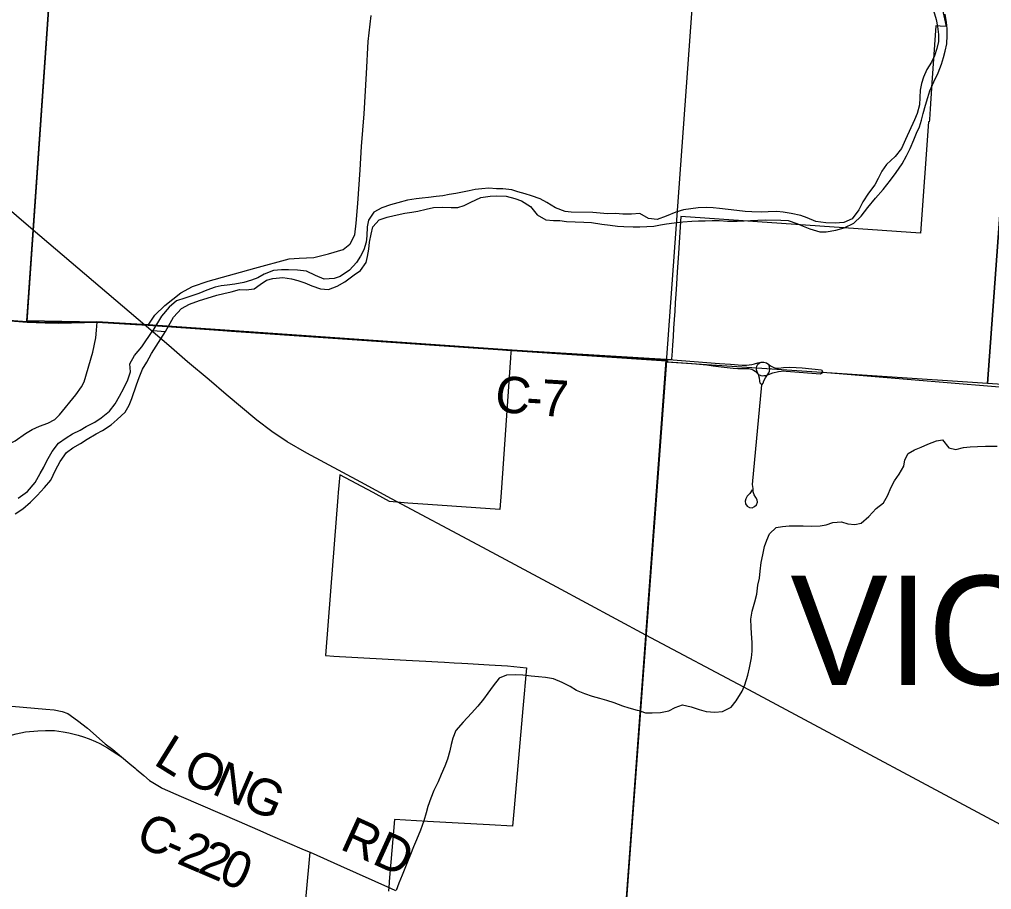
# Model space of a CAD drawing. Extents: x 0 to 34, y 0 to 22.
# Drawn here: x 2.165 to 3.682, y 15.435 to 16.793 of the extents above; entities that cross this region are included whole.
import ezdxf

# ---------------------------------------------------------------- set-up
doc = ezdxf.new("R2010")
doc.units = 0
for name, color, linetype in [('GM_X_City_Street', 7, 'Continuous'), ('GM_X_Corporation', 7, 'Continuous'), ('GM_X_County', 7, 'Continuous'), ('GM_X_County_Road', 7, 'Continuous'), ('GM_X_County_Road_Text', 7, 'Continuous'), ('GM_X_Minor_River', 7, 'Continuous'), ('GM_X_Rail_Line', 7, 'Continuous'), ('GM_X_Township_Road', 7, 'Continuous'), ('GM_X_Township_Text', 7, 'Continuous')]:
    doc.layers.add(name, color=color, linetype=linetype)

msp = doc.modelspace()

# ---------------------------------------------------------------- linework, layer by layer
at = {"layer": 'GM_X_City_Street'}
for p, q in [((2.1, 16.3267), (2.177, 16.3208)), ((2.2862, 16.3208), (2.346, 16.3171)), ((2.346, 16.3171), (2.356, 16.3165)), ((2.356, 16.3165), (2.366, 16.3159)), ((2.366, 16.3159), (2.4758, 16.3083)), ((2.4758, 16.3083), (2.4958, 16.3069)), ((2.4958, 16.3069), (2.8651, 16.2813)), ((2.8651, 16.2813), (2.912, 16.278)), ((2.912, 16.278), (2.925, 16.2771))]:
    msp.add_line(p, q, dxfattribs=at)
for points in [[(2.1, 16.1061), (2.1006, 16.1068), (2.1101, 16.1137), (2.1198, 16.1188), (2.1456, 16.129), (2.1584, 16.1355), (2.1745, 16.1467), (2.1851, 16.1533), (2.1964, 16.1584), (2.2094, 16.1632), (2.22, 16.1689), (2.2277, 16.1759), (2.2528, 16.2074), (2.2618, 16.2199), (2.266, 16.2274), (2.2797, 16.274), (2.2844, 16.2963), (2.2852, 16.3083), (2.2862, 16.3208)], [(2.177, 16.3208), (2.2054, 16.3195), (2.2266, 16.3194), (2.2862, 16.3208)], [(2.925, 16.2771), (2.934, 16.2765), (3.1745, 16.2606)], [(3.3184, 16.239), (3.316, 16.2432), (3.3151, 16.2465), (3.315, 16.249), (3.3156, 16.2519), (3.3172, 16.2551), (3.3193, 16.2568), (3.3222, 16.2584)], [(3.3325, 16.2385), (3.3346, 16.2416), (3.3354, 16.2442), (3.3359, 16.2476), (3.3356, 16.2509), (3.3343, 16.2548)], [(3.3232, 16.2229), (3.3207, 16.2255), (3.3204, 16.2294), (3.3199, 16.2332), (3.3184, 16.239)], [(3.3232, 16.2229), (3.3257, 16.2253), (3.3267, 16.2292), (3.3289, 16.234), (3.3325, 16.2385)], [(3.3083, 16.0592), (3.3047, 16.0532), (3.3007, 16.0489), (3.2985, 16.0451), (3.2976, 16.0413), (3.2979, 16.0372), (3.3006, 16.0336), (3.3043, 16.0313), (3.3084, 16.0311), (3.3122, 16.033), (3.315, 16.0357), (3.3167, 16.0399), (3.316, 16.0436), (3.3139, 16.0472), (3.3115, 16.0513), (3.31, 16.0559), (3.31, 16.0611), (3.3089, 16.0674), (3.3232, 16.2229)], [(2.1, 15.6513), (2.1025, 15.6529), (2.1199, 15.6632), (2.134, 15.6695), (2.1483, 15.6747), (2.1597, 15.6778), (2.1745, 15.681), (2.1937, 15.6829), (2.2057, 15.6834), (2.212, 15.6834), (2.2195, 15.6831), (2.233, 15.6813), (2.2422, 15.6795), (2.2567, 15.6757), (2.2652, 15.6731), (2.2738, 15.67), (2.2836, 15.666), (2.2905, 15.6627), (2.3025, 15.6563), (2.3241, 15.6421)]]:
    msp.add_lwpolyline(points, dxfattribs=at)
at = {"layer": 'GM_X_Corporation'}
for points in [[(4.3071, 20.9), (2.1, 20.9), (2.1, 14.1), (3.0169, 14.1), (3.0406, 14.4484), (3.1026, 15.287), (3.1745, 16.2606), (2.934, 16.2765), (2.366, 16.3159), (2.2862, 16.3208), (2.1768, 16.323), (2.2478, 17.3472), (2.3155, 18.3567), (3.8153, 18.2543), (3.8503, 18.7566), (3.8611, 18.9124), (3.8924, 19.3621), (3.9019, 19.4987), (3.9133, 19.6628), (3.9816, 20.645), (3.9912, 20.7822), (4.2975, 20.7549)], [(3.2481, 17.2693), (3.7496, 17.2367), (3.6755, 16.2252), (3.1745, 16.2581)], [(3.7496, 17.2367), (4.2556, 17.2022), (4.1846, 16.1905), (3.6755, 16.2252)], [(2.1, 16.3272), (2.1, 14.1), (3.0167, 14.1), (3.0404, 14.449), (3.1023, 15.2875), (3.1743, 16.2612), (2.9338, 16.2771), (2.3658, 16.3164), (2.2859, 16.3213), (2.2263, 16.32), (2.2052, 16.32), (2.1768, 16.3213)]]:
    msp.add_lwpolyline(points, close=True, dxfattribs=at)
for points in [[(2.1, 20.8993), (2.1, 16.3272), (2.1768, 16.3213), (2.1816, 16.3969), (2.2476, 17.3477), (2.2711, 17.6998), (2.2728, 17.718), (2.3153, 18.3572), (3.3358, 18.2876), (3.8151, 18.2549), (3.8501, 18.7572)], [(3.1023, 15.2875), (3.1743, 16.2612), (2.9338, 16.2771), (2.3658, 16.3164), (2.2859, 16.3213), (2.2263, 16.32), (2.2052, 16.32), (2.1768, 16.3213), (2.1816, 16.3969), (2.2476, 17.3477), (2.2711, 17.6998), (2.2728, 17.718), (2.3153, 18.3572), (3.3358, 18.2876), (3.8151, 18.2549), (3.8501, 18.7572)], [(3.8151, 18.2549), (3.3358, 18.2876), (2.3153, 18.3572), (2.2728, 17.718), (2.2711, 17.6998), (2.2476, 17.3477), (2.1816, 16.3969), (2.1768, 16.3213), (2.2052, 16.32), (2.2263, 16.32), (2.2859, 16.3213), (2.3658, 16.3164), (2.9338, 16.2771), (3.1743, 16.2612), (3.1023, 15.2875)], [(3.8151, 18.2549), (3.3358, 18.2876), (2.3153, 18.3572), (2.2728, 17.718), (2.2711, 17.6998), (2.2476, 17.3477), (2.1816, 16.3969), (2.1768, 16.3213), (2.2052, 16.32), (2.2263, 16.32), (2.2859, 16.3213), (2.3658, 16.3164), (2.9338, 16.2771), (3.1743, 16.2612), (3.1023, 15.2875)], [(6.5646, 18.0583), (6.0906, 18.0978), (6.0343, 18.1015), (5.9465, 18.1082), (5.8371, 18.1158), (5.5447, 18.1318), (4.9551, 18.1768), (4.7449, 18.1929), (4.5528, 18.2021), (4.3271, 18.2226), (4.1999, 18.2271), (3.8153, 18.2543), (2.3155, 18.3567), (2.2478, 17.3472), (2.1768, 16.323), (2.2862, 16.3208), (2.366, 16.3159), (2.934, 16.2765), (3.1745, 16.2606), (3.1026, 15.287), (3.0406, 14.4484), (3.0169, 14.1), (8.9, 14.1)], [(3.6049, 16.8109), (3.6112, 16.7822), (3.6112, 16.7822), (3.611, 16.7822), (3.6018, 16.7828), (3.5948, 16.7834), (3.5947, 16.7834), (3.5947, 16.7833), (3.5884, 16.6874), (3.5883, 16.6859), (3.5861, 16.6537), (3.5849, 16.6372), (3.5848, 16.6365), (3.5846, 16.6337), (3.5837, 16.6338), (3.5712, 16.4597), (3.1972, 16.4856), (3.1934, 16.4287), (3.1915, 16.399), (3.1909, 16.3901), (3.1903, 16.3801), (3.1893, 16.3645), (3.1884, 16.3512), (3.1875, 16.338), (3.1867, 16.3248), (3.1858, 16.3115), (3.1849, 16.2983), (3.1841, 16.2851), (3.1829, 16.268), (3.1827, 16.2643), (3.1825, 16.2621), (2.9487, 16.2762), (2.9321, 16.2772), (2.9318, 16.2733), (2.9312, 16.2653), (2.9165, 16.0546), (2.9147, 16.0283), (2.8022, 16.0361), (2.7709, 16.0382), (2.7423, 16.041), (2.7218, 16.0521), (2.717, 16.0546), (2.665, 16.0823), (2.6625, 16.0546), (2.6619, 16.0474), (2.6504, 15.9008), (2.6425, 15.8002), (2.6554, 15.7995), (2.6646, 15.799), (2.6741, 15.7984), (2.6836, 15.7979), (2.693, 15.7974), (2.7025, 15.7968), (2.7119, 15.7963), (2.7217, 15.7957), (2.7308, 15.7952), (2.7403, 15.7947), (2.7497, 15.7942), (2.7592, 15.7936), (2.7686, 15.7931), (2.7781, 15.7926), (2.7885, 15.792), (2.7989, 15.7914), (2.8084, 15.7909), (2.8178, 15.7903), (2.8283, 15.7897), (2.8435, 15.7889), (2.8552, 15.7882), (2.8647, 15.7877), (2.8978, 15.7858), (2.9267, 15.7842), (2.956, 15.7809), (2.9504, 15.7174), (2.9369, 15.5624), (2.9343, 15.5336), (2.8985, 15.5357), (2.8496, 15.5385), (2.8018, 15.5413), (2.7501, 15.5443), (2.7417, 15.4475), (2.7417, 15.4453), (2.7408, 15.4323)]]:
    msp.add_lwpolyline(points, dxfattribs=at)
at = {"layer": 'GM_X_County'}
msp.add_lwpolyline([(3.1023, 15.2875), (3.1743, 16.2612), (2.9338, 16.2771), (2.3658, 16.3164), (2.2859, 16.3213), (2.2263, 16.32), (2.2052, 16.32), (2.1768, 16.3213), (2.1816, 16.3969), (2.2476, 17.3477), (2.2711, 17.6998), (2.2728, 17.718), (2.3153, 18.3572), (3.3358, 18.2876), (3.8151, 18.2549)], dxfattribs=at)
at = {"layer": 'GM_X_County_Road'}
for p, q in [((2.2862, 16.3208), (2.346, 16.3171)), ((2.346, 16.3171), (2.356, 16.3165)), ((2.356, 16.3165), (2.366, 16.3159)), ((2.366, 16.3159), (2.4758, 16.3083)), ((2.4758, 16.3083), (2.4958, 16.3069)), ((2.4958, 16.3069), (2.8651, 16.2813)), ((2.8651, 16.2813), (2.912, 16.278)), ((2.912, 16.278), (2.925, 16.2771)), ((3.4186, 16.2428), (3.4691, 16.2386)), ((2.508, 15.5409), (2.545, 15.5248))]:
    msp.add_line(p, q, dxfattribs=at)
for points in [[(2.925, 16.2771), (2.934, 16.2765), (3.1657, 16.2612), (3.1745, 16.2606)], [(3.1745, 16.2606), (3.1781, 16.2623), (3.2377, 16.2577), (3.2573, 16.2563), (3.2746, 16.2551), (3.2926, 16.2538), (3.2997, 16.2539), (3.3076, 16.2548), (3.312, 16.2559), (3.3173, 16.2575), (3.3222, 16.2584)], [(3.1745, 16.2606), (3.1771, 16.259), (3.2146, 16.2564), (3.2375, 16.2541), (3.2476, 16.2527), (3.2601, 16.251), (3.2692, 16.2498), (3.2786, 16.249), (3.286, 16.2486), (3.2955, 16.2487), (3.3031, 16.2484), (3.3072, 16.2475), (3.3104, 16.246), (3.3128, 16.2441), (3.3145, 16.2425), (3.3184, 16.239)], [(3.3222, 16.2584), (3.3265, 16.2585), (3.3307, 16.2571), (3.3343, 16.2548)], [(3.3343, 16.2548), (3.3368, 16.2526), (3.3409, 16.2503), (3.3446, 16.2491), (3.3493, 16.2491), (3.3571, 16.2499), (3.3669, 16.2503), (3.3772, 16.2501), (3.3863, 16.2495), (3.4163, 16.2463), (3.4186, 16.2428)], [(3.3184, 16.239), (3.3218, 16.2375), (3.3245, 16.2372), (3.3266, 16.2373), (3.33, 16.2376), (3.3325, 16.2385)], [(3.3325, 16.2385), (3.334, 16.2391), (3.3404, 16.2418), (3.3493, 16.2439), (3.3578, 16.2446), (3.3615, 16.2444), (3.4152, 16.2402), (3.4186, 16.2428)], [(3.4691, 16.2386), (3.8317, 16.2085), (3.8733, 16.2068)], [(2.153, 15.7212), (2.2064, 15.7167), (2.2194, 15.7153), (2.2316, 15.7131), (2.2403, 15.7098), (2.2556, 15.6988), (2.271, 15.6867), (2.299, 15.6626), (2.3105, 15.6534), (2.3241, 15.6421)], [(2.3241, 15.6421), (2.3372, 15.631), (2.3454, 15.6242), (2.347, 15.6229)], [(2.347, 15.6229), (2.359, 15.613), (2.368, 15.6054), (2.3782, 15.5987), (2.386, 15.5943), (2.3878, 15.5934)], [(2.3878, 15.5934), (2.4172, 15.5804), (2.508, 15.5409)], [(2.545, 15.5248), (2.5561, 15.52), (2.6094, 15.4971)], [(2.5479, 14.5441), (2.5748, 14.9604), (2.5921, 15.2034), (2.6186, 15.4932)], [(2.6094, 15.4971), (2.6186, 15.4932), (2.6658, 15.4721), (2.7439, 15.4371), (2.7518, 15.4334)]]:
    msp.add_lwpolyline(points, dxfattribs=at)
at = {"layer": 'GM_X_Minor_River'}
for points in [[(3.5914, 16.8072), (3.5954, 16.7934), (3.5975, 16.7824), (3.5992, 16.7702), (3.599, 16.7589), (3.5966, 16.7483), (3.5931, 16.7369), (3.5884, 16.7267), (3.581, 16.7155), (3.5756, 16.7034), (3.5724, 16.6932), (3.5707, 16.683), (3.5698, 16.6716), (3.5693, 16.6602), (3.566, 16.6466), (3.5617, 16.6368), (3.5477, 16.6062), (3.5414, 16.5919), (3.5314, 16.5795), (3.518, 16.5668)], [(3.1749, 16.4744), (3.1867, 16.4761), (3.1999, 16.4774), (3.214, 16.4784), (3.2246, 16.479), (3.2348, 16.4792), (3.2461, 16.4794), (3.2571, 16.4793), (3.2696, 16.4787), (3.2851, 16.4785), (3.2961, 16.4788), (3.3059, 16.4794), (3.3287, 16.4806), (3.3529, 16.4802), (3.3646, 16.4793), (3.3782, 16.4746), (3.3879, 16.4706), (3.3981, 16.4663), (3.4139, 16.4619), (3.4238, 16.4618), (3.4389, 16.4642), (3.4519, 16.4682), (3.4671, 16.4756), (3.4786, 16.4861), (3.4886, 16.4996), (3.5006, 16.5143), (3.5125, 16.5278), (3.5241, 16.5424), (3.5329, 16.5544), (3.5426, 16.568), (3.5492, 16.5804), (3.5547, 16.5921), (3.5605, 16.6053), (3.5648, 16.6158), (3.5692, 16.626), (3.5727, 16.6362), (3.5751, 16.6468), (3.5787, 16.6597), (3.5823, 16.6718), (3.5858, 16.682), (3.5917, 16.6959), (3.5984, 16.7103), (3.6038, 16.7235), (3.607, 16.7341), (3.6094, 16.7439), (3.6119, 16.7556), (3.6128, 16.7682), (3.6126, 16.7788), (3.6116, 16.789), (3.6095, 16.8016)], [(3.518, 16.5668), (3.5106, 16.5566), (3.5052, 16.5449), (3.4997, 16.5351), (3.4901, 16.5224), (3.4808, 16.5088), (3.4746, 16.496), (3.4642, 16.4821), (3.4512, 16.4766), (3.438, 16.4756), (3.4232, 16.4759), (3.4077, 16.478), (3.3942, 16.4835), (3.3844, 16.4874), (3.3693, 16.4903), (3.3568, 16.4927), (3.347, 16.4936), (3.3334, 16.493), (3.3224, 16.4924), (3.308, 16.493), (3.2974, 16.4935), (3.2842, 16.4949), (3.271, 16.4966), (3.2574, 16.4983), (3.2476, 16.4992), (3.237, 16.4997), (3.2241, 16.4991), (3.2127, 16.4977), (3.201, 16.496), (3.1892, 16.4928), (3.1743, 16.4865), (3.1599, 16.481), (3.1467, 16.4827), (3.1332, 16.4905), (3.1203, 16.4895), (3.1066, 16.4893), (3.0949, 16.4903), (3.0828, 16.4901), (3.0711, 16.491), (3.0598, 16.4919), (3.0261, 16.4924), (3.0163, 16.4936), (3.0016, 16.4992), (2.9881, 16.5077), (2.9776, 16.5132), (2.964, 16.5183), (2.9542, 16.5211), (2.9429, 16.5243), (2.9331, 16.5274), (2.9191, 16.5288), (2.9093, 16.5289), (2.8972, 16.5298), (2.8866, 16.5288), (2.8763, 16.5278), (2.8668, 16.5257), (2.8562, 16.5236), (2.846, 16.5218), (2.8354, 16.5201), (2.8255, 16.5183), (2.8153, 16.5169), (2.8035, 16.5152), (2.7933, 16.5142), (2.7838, 16.5132), (2.7705, 16.5111), (2.7557, 16.5071), (2.7439, 16.5039), (2.7306, 16.4991), (2.718, 16.4928), (2.7099, 16.48), (2.7075, 16.4698), (2.7073, 16.4558), (2.706, 16.4456), (2.7024, 16.4338), (2.6974, 16.424), (2.6908, 16.4139), (2.68, 16.4019), (2.6655, 16.3922), (2.656, 16.3889), (2.6405, 16.388), (2.6269, 16.3935), (2.613, 16.4002), (2.599, 16.4019), (2.585, 16.4025), (2.5741, 16.4026), (2.5612, 16.4013), (2.5471, 16.3958), (2.5368, 16.3898), (2.5273, 16.3862), (2.5151, 16.3829), (2.5011, 16.3801), (2.4893, 16.3784), (2.4799, 16.3773), (2.4704, 16.3752), (2.4574, 16.3708), (2.4449, 16.3657), (2.4342, 16.3617), (2.4232, 16.3584), (2.4103, 16.354), (2.3984, 16.3443), (2.3868, 16.3301), (2.3732, 16.3077)], [(2.3931, 16.3064), (2.4054, 16.3287), (2.418, 16.3421), (2.4306, 16.3488), (2.4459, 16.3547), (2.458, 16.3583), (2.4732, 16.363), (2.4839, 16.3655), (2.4956, 16.3684), (2.5085, 16.3716), (2.5188, 16.3715), (2.5313, 16.3728), (2.5408, 16.3795), (2.5504, 16.3866), (2.5606, 16.3891), (2.5758, 16.3904), (2.5894, 16.3887), (2.5996, 16.3859), (2.6101, 16.3824), (2.6214, 16.3777), (2.6346, 16.3729), (2.6474, 16.3716), (2.6608, 16.3771), (2.673, 16.3838), (2.6875, 16.3946), (2.6971, 16.4017), (2.7059, 16.4137), (2.708, 16.4235), (2.71, 16.4349), (2.7113, 16.4455), (2.7138, 16.458), (2.7166, 16.4697), (2.7262, 16.4806), (2.7387, 16.4846), (2.7497, 16.4871), (2.7664, 16.491), (2.7771, 16.4928), (2.7865, 16.4942), (2.7998, 16.4974), (2.8109, 16.4999), (2.8249, 16.5005), (2.8385, 16.4999), (2.8491, 16.4998), (2.859, 16.503), (2.8692, 16.5082), (2.8852, 16.5152), (2.8993, 16.5177), (2.9095, 16.5179), (2.9246, 16.5173), (2.9382, 16.5141), (2.9484, 16.5105), (2.9626, 16.5016), (2.9727, 16.4882), (2.9866, 16.4808), (2.9983, 16.4795), (3.0081, 16.4793), (3.0187, 16.478), (3.0319, 16.4775), (3.0459, 16.4769), (3.0576, 16.4764), (3.0739, 16.4739), (3.0867, 16.4722), (3.0981, 16.4709), (3.1079, 16.4704), (3.1226, 16.4698), (3.1332, 16.4696), (3.1442, 16.4702), (3.1548, 16.4708), (3.1651, 16.4726), (3.1749, 16.4744)], [(2.1583, 16.0214), (2.1704, 16.0293), (2.1822, 16.0395), (2.1925, 16.0504), (2.2043, 16.0628), (2.2138, 16.0742), (2.2215, 16.0897), (2.2284, 16.1033), (2.2387, 16.1173), (2.2485, 16.1244), (2.2603, 16.1316), (2.2709, 16.1383), (2.2846, 16.1462), (2.2945, 16.1515), (2.3081, 16.1605), (2.3176, 16.1688), (2.3298, 16.1805), (2.3363, 16.1911), (2.3405, 16.2017), (2.3478, 16.2232), (2.3517, 16.2342), (2.3571, 16.2475), (2.3636, 16.2584), (2.3712, 16.2717), (2.3931, 16.3064)], [(2.163, 16.046), (2.1774, 16.0566), (2.1896, 16.0705), (2.1976, 16.0845), (2.2033, 16.0944), (2.2079, 16.1042), (2.216, 16.1189), (2.2259, 16.1318), (2.2377, 16.1401), (2.2479, 16.1464), (2.2597, 16.1524), (2.2692, 16.1581), (2.2824, 16.1648), (2.2927, 16.1712), (2.3056, 16.1818), (2.3144, 16.1935), (2.3213, 16.2052), (2.3278, 16.2177), (2.3339, 16.2309), (2.3381, 16.2434), (2.3374, 16.2556), (2.3443, 16.2688), (2.3561, 16.2824), (2.3732, 16.3077)], [(2.3732, 16.3077), (2.3931, 16.3064)], [(3.1346, 15.7136), (3.1421, 15.7108), (3.1523, 15.711), (3.1652, 15.7112), (3.1785, 15.7137), (3.1884, 15.7193), (3.1994, 15.7233), (3.213, 15.7204), (3.2254, 15.7161), (3.2364, 15.7129), (3.25, 15.7116), (3.2621, 15.7129), (3.2754, 15.7196), (3.2835, 15.7297), (3.2928, 15.7444), (3.2968, 15.7546), (3.3015, 15.7697), (3.3043, 15.781), (3.3072, 15.7969), (3.3081, 15.8072), (3.3083, 15.8208), (3.3074, 15.8349), (3.3067, 15.8444), (3.3065, 15.8569), (3.3082, 15.8694), (3.3126, 15.8841), (3.3154, 15.8963), (3.3171, 15.9099), (3.3196, 15.9212), (3.3209, 15.9319), (3.3222, 15.9455), (3.325, 15.9576), (3.3278, 15.9705), (3.331, 15.9803), (3.3353, 15.9905), (3.3457, 16.0002), (3.3555, 16.002), (3.3661, 16.0026), (3.376, 16.0028), (3.3881, 16.0027), (3.4009, 16.0021), (3.4142, 16.0027), (3.4237, 16.0044), (3.4343, 16.0081), (3.4476, 16.009), (3.4574, 16.0059), (3.4687, 16.005), (3.4786, 16.0071), (3.4905, 16.0172), (3.5016, 16.0299), (3.5131, 16.0389), (3.5197, 16.0498), (3.5252, 16.0634), (3.5303, 16.0732), (3.5376, 16.0837), (3.545, 16.0958), (3.5466, 16.106), (3.5517, 16.1158), (3.5616, 16.1213), (3.5719, 16.1257), (3.5825, 16.1302), (3.5959, 16.1357), (3.6053, 16.1371), (3.6154, 16.1248), (3.6259, 16.122), (3.6381, 16.1252), (3.6483, 16.1262), (3.6601, 16.1268), (3.6726, 16.1274), (3.6907, 16.127)], [(3.1346, 15.7136), (3.1293, 15.7145), (3.1165, 15.7179), (3.1067, 15.7214), (3.0931, 15.7264), (3.0814, 15.7303), (3.0705, 15.733), (3.0592, 15.7365), (3.0471, 15.7404), (3.0343, 15.7458), (3.0241, 15.7519), (3.0117, 15.7581), (2.9981, 15.7638), (2.986, 15.7662), (2.975, 15.767), (2.9633, 15.7682), (2.9505, 15.7698), (2.9388, 15.7703), (2.9251, 15.7696), (2.9134, 15.7647), (2.9042, 15.753), (2.8958, 15.7417), (2.889, 15.7319), (2.8802, 15.7213), (2.8703, 15.7104), (2.8574, 15.6964), (2.8459, 15.6832), (2.8413, 15.6711), (2.8386, 15.6612), (2.8367, 15.6514), (2.8332, 15.6385), (2.829, 15.6275), (2.8232, 15.6143), (2.8186, 15.6033), (2.8117, 15.5893), (2.8071, 15.5775), (2.8025, 15.5643), (2.7998, 15.5548), (2.7959, 15.5423), (2.7909, 15.5276), (2.7844, 15.5124), (2.7798, 15.5018), (2.7752, 15.4897), (2.7706, 15.4783), (2.7663, 15.4677), (2.7621, 15.4575), (2.7571, 15.4447), (2.7529, 15.4333)]]:
    msp.add_lwpolyline(points, dxfattribs=at)
at = {"layer": 'GM_X_Rail_Line'}
for points in [[(2.1864, 16.4643), (2.134, 16.5093), (2.1, 16.5331)], [(2.3635, 16.3138), (2.3606, 16.3162), (2.1864, 16.4643)], [(3.1426, 15.8323), (3.0036, 15.907), (2.8802, 15.9729), (2.7456, 16.0452), (2.6977, 16.0709), (2.6132, 16.1164), (2.583, 16.134), (2.5587, 16.1502), (2.5353, 16.1678), (2.4877, 16.2077), (2.4612, 16.2305), (2.4274, 16.2591), (2.3979, 16.2842), (2.3635, 16.3138)], [(5.9528, 14.1), (5.6437, 14.2982), (5.4789, 14.4041), (4.8128, 14.8326), (4.5194, 15.0215), (4.222, 15.2127), (4.0411, 15.3289), (3.919, 15.4076), (3.8544, 15.4493), (3.8245, 15.4671), (3.7478, 15.5086), (3.3032, 15.7468), (3.1426, 15.8323)]]:
    msp.add_lwpolyline(points, dxfattribs=at)
at = {"layer": 'GM_X_Township_Road'}
msp.add_lwpolyline([(2.366, 16.3159), (2.3765, 16.3317), (2.3918, 16.3469), (2.4169, 16.3668), (2.435, 16.3765), (2.4596, 16.3849), (2.5323, 16.4049), (2.5858, 16.4196), (2.6015, 16.4205), (2.6243, 16.4219), (2.6471, 16.4275), (2.6699, 16.4342), (2.6805, 16.4427), (2.6813, 16.4433), (2.6882, 16.4569), (2.6902, 16.4752), (2.6931, 16.5063), (2.6968, 16.5584), (2.6985, 16.5949), (2.7027, 16.6462), (2.7068, 16.7093), (2.709, 16.7591), (2.7138, 16.7998)], dxfattribs=at)

# ---------------------------------------------------------------- texts
at = {"layer": 'GM_X_County_Road_Text'}
for s, height, rotation, p in [('C', 0.0568, 353.4404, (2.9049, 16.1821)), ('7', 0.0568, 356.5399, (2.9779, 16.175)), ('-', 0.0568, 356.4281, (2.9545, 16.1765)), ('L', 0.0568, 328.1954, (2.3725, 15.6314)), ('O', 0.0568, 337.1343, (2.4172, 15.6045)), ('N', 0.0568, 336.5986, (2.4631, 15.5851)), ('G', 0.0568, 336.5953, (2.509, 15.5653)), ('C', 0.0568, 335.1126, (2.3435, 15.5063)), ('RD', 0.05682, 335.6372, (2.6632, 15.4989)), ('2', 0.0568, 336.6098, (2.4087, 15.4766)), ('-', 0.0568, 336.3058, (2.3871, 15.4861)), ('2', 0.0568, 336.7665, (2.441, 15.4627)), ('0', 0.0568, 336.7982, (2.4732, 15.4488))]:
    msp.add_text(s, height=height, rotation=rotation, dxfattribs=at).set_placement(p)
at = {"layer": 'GM_X_Township_Text'}
msp.add_text('VIOLET', height=0.17045, rotation=0, dxfattribs=at).set_placement((3.368, 15.7544))

doc.saveas('drawing.dxf')
